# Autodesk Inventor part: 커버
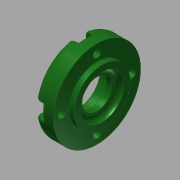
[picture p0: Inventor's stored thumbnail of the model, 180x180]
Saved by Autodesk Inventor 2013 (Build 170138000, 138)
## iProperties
Created: 2015-11
Part Number: 커버
Material: 알루미늄 6061
Document SubType Name: Modeling
Designer: mduedu
Density: 1 g/cm^3
Author: mduedu
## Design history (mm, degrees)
sketch "스케치1"
  geometry: L1 (-7, 0)-(7, 0); L2 (-7, 0)-(-7, 25); L3 (-7, 25)-(4, 25); L4 (4, 25)-(4, 16); L5 (4, 16)-(7, 16); L6 (7, 16)-(7, 0); 2 further points
  constraints: 12 end point, 3 perpendicular, 2 parallel, 1 coincident, 1 horizontal, 1 midpoint
  dimensions: "d0" = 14 distance of L1.start L1.end; "d1" = 50 diameter of L3 L1; "d2" = 3 distance of L4.end L5.end; "d3" = 32 diameter of L5 L1
revolve "회전1" sketch "스케치1" stored, may be unused: angle "d4" = 90 deg
hole "구멍1" diameter "d7" = 25; stored, may be unused: countersink angle "d11" = 90 deg, drill point angle "d13" = 0 deg; dims "d5" = 10, "d6" = 10, "d8" = 6, "d9" = 4, "d10" = 2, "d12" = 3
hole "구멍2" diameter "d16" = 25; stored, may be unused: countersink angle "d20" = 90 deg, drill point angle "d22" = 0 deg; dims "d17" = 6, "d18" = 4, "d19" = 2, "d21" = 7.7, "d58" = 10, "d59" = 10
hole "구멍3" diameter "d25" = 17; stored, may be unused: countersink angle "d29" = 90 deg, drill point angle "d31" = 0 deg; dims "d23" = 10, "d24" = 10, "d26" = 6, "d27" = 4, "d28" = 2, "d30" = 4.2
chamfer "모따기1" distance "d32" = 0.6; stored, may be unused: second distance "d33" = 2, angle "d34" = 30 deg
fillet "모깎기1" dims "d35" = 0.3
fillet "모깎기2" dims "d36" = 3
fillet "모깎기3" dims "d37" = 3
fillet "모깎기4" dims "d38" = 0.3
sketch "스케치2" dims "d39" = 40
  geometry: 6 further points
  constraints: 2 vertical alignment, 1 coincident, 7 other
  dimensions: "d42" = 360 deg dimension on point (0, 0) point (0, 20) (derived)
sketch "스케치3"
  geometry: 4 further points
hole "구멍4" sketch "스케치3" at (-20, 0), (0, -20), (20, 0), (0, 20) diameter "d44" = 4.5; stored, may be unused: countersink angle "d48" = 90 deg, drill point angle "d50" = 0 deg; dims "d45" = 6, "d46" = 8, "d47" = 4.6, "d49" = 8
sketch "스케치4"
  geometry: L1 (-4, 0)-(-4, -4.678); L2 (4, 0)-(4, -4.678); A1 r 4 centre (0, 0) between (3.621, -1.7) and (-3.621, -1.7) reference; A2 r 25 centre (0, 20) between (-4, -4.678) and (4, -4.678) reference; 1 further point
  constraints: 4 end point, 4 point on circle, 2 tangent, 1 parallel, 1 vertical
extrude "돌출1" cut sketch "스케치4" stored distance "d51" = 0; taper "d52" = 0 deg
fillet "모깎기5" dims "d56" = 0.3
fillet "모깎기6" dims "d57" = 1
node "솔리드1"
pattern_circular "원형 패턴1" dims angle "d54" = 360 deg
